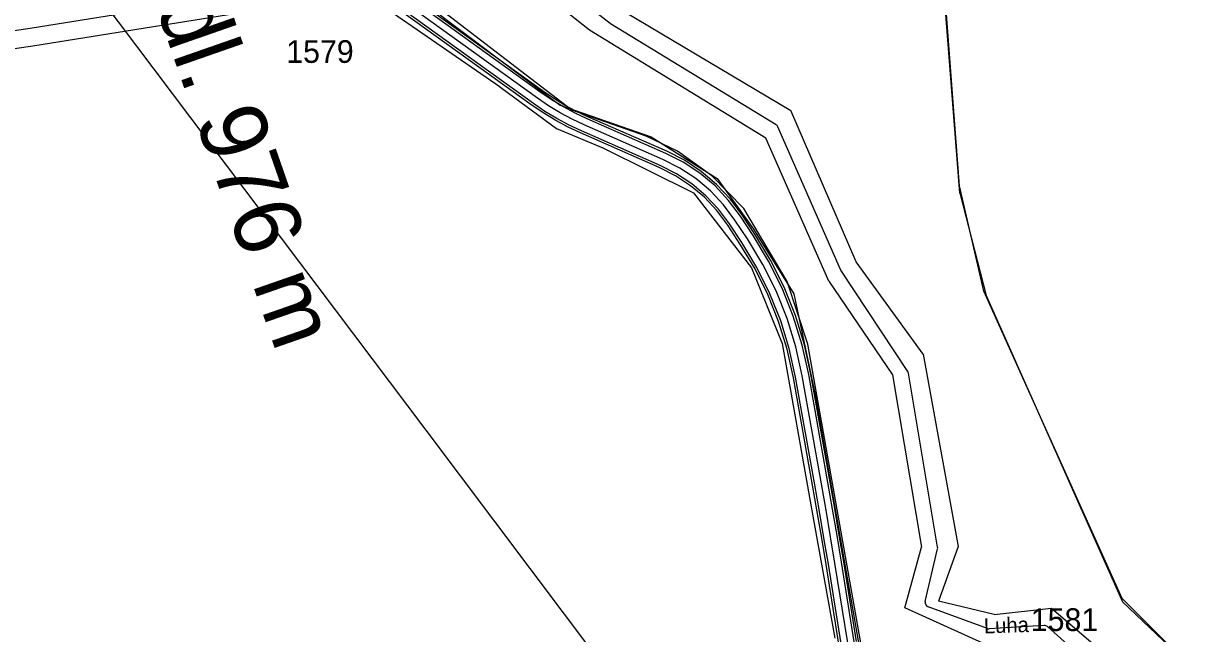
# Model space of a CAD drawing. Extents: x -510185 to -506993, y -1126306 to -1123642.
# Drawn here: x -508784.2 to -508521.1, y -1125749.7 to -1125612.6 of the extents above; entities that cross this region are included whole.
import ezdxf

# ---------------------------------------------------------------- set-up
doc = ezdxf.new("R2010")
doc.units = 0
for name, color, linetype in [('parcelni hranice', 7, 'Continuous'), ('popis cesty', 7, 'Continuous'), ('u_cesta45', 7, 'Continuous'), ('u_osa45', 7, 'Continuous'), ('u_plyn ochranné pásmo', 7, 'Continuous'), ('u_plyn VTL', 7, 'Continuous'), ('u_tok Luha', 7, 'Continuous'), ('u_vysadba_oseti', 7, 'Continuous'), ('ˇ2', 7, 'Continuous'), ('ˇ7', 7, 'Continuous')]:
    doc.layers.add(name, color=color, linetype=linetype)

msp = doc.modelspace()

# ---------------------------------------------------------------- linework, layer by layer
at = {"layer": 'parcelni hranice'}
for p, q in [((-508656.79, -1125614.14), (-508689.34, -1125588.22)), ((-508573.48, -1125650.78), (-508577.96, -1125593.25)), ((-508769.78, -1125602.99), (-508693.62, -1125704.05)), ((-508660.76, -1125632.06), (-508698.05, -1125603.52)), ((-508654, -1125606.86), (-508611.54, -1125632.17)), ((-508704.46, -1125607.9), (-508677.88, -1125626.19)), ((-508617.14, -1125638.37), (-508656.79, -1125614.14)), ((-508677.88, -1125626.19), (-508664.23, -1125636.19)), ((-508644.09, -1125637.9), (-508660.76, -1125632.06)), ((-508596.84, -1125666.2), (-508611.54, -1125632.17)), ((-508664.23, -1125636.19), (-508653.81, -1125640.54)), ((-508637.04, -1125641.34), (-508644.09, -1125637.9)), ((-508602.93, -1125670.51), (-508617.14, -1125638.37)), ((-508653.81, -1125640.54), (-508633.42, -1125650.65)), ((-508629.31, -1125646.84), (-508637.04, -1125641.34)), ((-508622.09, -1125654.23), (-508629.31, -1125646.84)), ((-508633.42, -1125650.65), (-508620.35, -1125667.54)), ((-508573.48, -1125650.78), (-508567.57, -1125673.74)), ((-508612.34, -1125670.63), (-508622.09, -1125654.23)), ((-508620.35, -1125667.54), (-508613.43, -1125684.51)), ((-508581.73, -1125686.94), (-508596.84, -1125666.2)), ((-508607.7, -1125684.72), (-508612.34, -1125670.63)), ((-508602.93, -1125670.51), (-508588.62, -1125691.57)), ((-508567.57, -1125673.74), (-508536.92, -1125742.59)), ((-508613.43, -1125684.51), (-508606.96, -1125721.26)), ((-508594.29, -1125760.02), (-508607.7, -1125684.72)), ((-508581.73, -1125686.94), (-508573.88, -1125730.19)), ((-508588.62, -1125691.57), (-508582.09, -1125730.32)), ((-508693.62, -1125704.05), (-508617.45, -1125805.11)), ((-508606.96, -1125721.26), (-508601.58, -1125750.78)), ((-508585.87, -1125743.98), (-508582.09, -1125730.32)), ((-508573.88, -1125730.19), (-508578.29, -1125742.45)), ((-508567.5, -1125752.28), (-508585.87, -1125743.98)), ((-508565.8, -1125745.45), (-508578.29, -1125742.45)), ((-508565.8, -1125745.45), (-508552.85, -1125744.04)), ((-508552.85, -1125744.04), (-508538.06, -1125756.62)), ((-508522.69, -1125756.07), (-508536.92, -1125742.59))]:
    msp.add_line(p, q, dxfattribs=at)
at = {"layer": 'u_cesta45'}
for points in [[(-508597.23, -1125751.59), (-508600.11, -1125733.68), (-508601.09, -1125727.71), (-508602.1, -1125721.74), (-508603.15, -1125715.79), (-508607.49, -1125691.53), (-508608.95, -1125684.92), (-508610.95, -1125678.43), (-508613.47, -1125672.12), (-508616.5, -1125666.03), (-508620, -1125660.24), (-508622.86, -1125655.92), (-508625.5, -1125652.38), (-508628.56, -1125649.13), (-508631.97, -1125646.26), (-508635.7, -1125643.8), (-508639.63, -1125641.8), (-508657.37, -1125634.03), (-508660.07, -1125632.77), (-508662.68, -1125631.37), (-508665.21, -1125629.83), (-508667.68, -1125628.16), (-508701.21, -1125604.02)], [(-508596.74, -1125751.51), (-508599.62, -1125733.6), (-508600.6, -1125727.63), (-508601.61, -1125721.66), (-508602.66, -1125715.7), (-508607, -1125691.43), (-508608.46, -1125684.8), (-508610.48, -1125678.26), (-508613.02, -1125671.91), (-508616.06, -1125665.79), (-508619.58, -1125659.97), (-508622.45, -1125655.63), (-508625.12, -1125652.06), (-508628.22, -1125648.77), (-508631.67, -1125645.86), (-508635.44, -1125643.36), (-508639.42, -1125641.34), (-508657.16, -1125633.58), (-508659.85, -1125632.32), (-508662.43, -1125630.93), (-508664.94, -1125629.41), (-508667.39, -1125627.75), (-508700.91, -1125603.62)], [(-508600.69, -1125752.11), (-508603.57, -1125734.24), (-508604.54, -1125728.29), (-508605.55, -1125722.34), (-508606.6, -1125716.4), (-508610.92, -1125692.22), (-508612.33, -1125685.82), (-508614.25, -1125679.6), (-508616.67, -1125673.55), (-508619.57, -1125667.72), (-508622.96, -1125662.11), (-508625.72, -1125657.93), (-508628.18, -1125654.63), (-508630.97, -1125651.68), (-508634.07, -1125649.07), (-508637.46, -1125646.83), (-508641.13, -1125644.96), (-508658.82, -1125637.22), (-508661.64, -1125635.89), (-508664.42, -1125634.41), (-508667.11, -1125632.78), (-508669.69, -1125631.02), (-508703.32, -1125606.82)], [(-508600.2, -1125752.04), (-508603.07, -1125734.16), (-508604.05, -1125728.2), (-508605.06, -1125722.26), (-508606.11, -1125716.31), (-508610.43, -1125692.12), (-508611.85, -1125685.69), (-508613.78, -1125679.43), (-508616.21, -1125673.34), (-508619.13, -1125667.48), (-508622.54, -1125661.84), (-508625.31, -1125657.65), (-508627.8, -1125654.31), (-508630.63, -1125651.32), (-508633.77, -1125648.67), (-508637.21, -1125646.39), (-508640.92, -1125644.51), (-508658.61, -1125636.77), (-508661.42, -1125635.45), (-508664.17, -1125633.97), (-508666.84, -1125632.36), (-508669.4, -1125630.61), (-508703.02, -1125606.42)]]:
    msp.add_lwpolyline(points, dxfattribs=at)
at = {"layer": 'u_osa45'}
msp.add_lwpolyline([(-508598.72, -1125751.81), (-508601.59, -1125733.92), (-508602.57, -1125727.96), (-508603.58, -1125722), (-508604.63, -1125716.05), (-508608.96, -1125691.82), (-508610.4, -1125685.31), (-508612.37, -1125678.93), (-508614.84, -1125672.73), (-508617.82, -1125666.76), (-508621.27, -1125661.04), (-508624.08, -1125656.78), (-508626.65, -1125653.35), (-508629.59, -1125650.23), (-508632.87, -1125647.46), (-508636.45, -1125645.1), (-508640.28, -1125643.15), (-508657.99, -1125635.4), (-508660.74, -1125634.11), (-508663.42, -1125632.67), (-508666.03, -1125631.1), (-508668.54, -1125629.38), (-508702.11, -1125605.22)], dxfattribs=at)
at = {"layer": 'u_plyn ochranné pásmo'}
msp.add_lwpolyline([(-508215.72, -1125512.32), (-508356.96, -1125534.53), (-508472.31, -1125551.39), (-508597.98, -1125572.31), (-508671.06, -1125599.9), (-508782.04, -1125617.67), (-508874.62, -1125631.18), (-508973.18, -1125645.99), (-509071.95, -1125660.86), (-509155.57, -1125674.9), (-509219.48, -1125685.66), (-509328.98, -1125704.41)], dxfattribs=at)
at = {"layer": 'u_plyn VTL'}
msp.add_lwpolyline([(-508672.09, -1125596.01), (-508782.65, -1125613.72), (-508875.21, -1125627.22), (-508973.78, -1125642.03), (-509072.58, -1125656.91), (-509156.23, -1125670.95), (-509220.15, -1125681.72)], dxfattribs=at)
at = {"layer": 'u_tok Luha'}
for p, q in [((-508652.19, -1125612.59), (-508703.37, -1125572.82)), ((-508614.84, -1125635.36), (-508652.1, -1125612.66)), ((-508600.36, -1125667.89), (-508614.44, -1125635.81)), ((-508585.18, -1125690.84), (-508600.28, -1125668.04)), ((-508578.49, -1125730.31), (-508585.03, -1125691.23)), ((-508581.26, -1125742.56), (-508578.5, -1125730.7)), ((-508567.28, -1125748.63), (-508580.63, -1125743.73)), ((-508554.5, -1125747.92), (-508566.87, -1125748.69)), ((-508541.92, -1125758.71), (-508553.78, -1125748.18))]:
    msp.add_line(p, q, dxfattribs=at)
for centre, start, end in [((-508651.58, -1125611.8), 232.1477, 238.6429), ((-508615.36, -1125636.22), 23.6973, 58.6429), ((-508599.45, -1125667.49), 203.6973, 213.5213), ((-508586.01, -1125691.39), 9.4969, 33.5213), ((-508579.47, -1125730.47), 346.8866, 9.4969), ((-508580.29, -1125742.79), 166.8866, 249.8293), ((-508566.93, -1125747.7), 249.8293, 273.5562), ((-508554.44, -1125748.92), 48.3665, 93.5562)]:
    msp.add_arc(centre, 1, start, end, dxfattribs=at)
at = {"layer": 'u_vysadba_oseti'}
for points in [[(-508767.46, -1125346.61), (-508757.41, -1125358.61), (-508747.36, -1125374.17), (-508745.73, -1125388.11), (-508747.68, -1125398.16), (-508754.81, -1125406.59), (-508777.51, -1125426.69), (-508778.48, -1125432.2), (-508749.95, -1125485.37), (-508739.57, -1125510.01), (-508727.9, -1125560.91), (-508714.29, -1125586.85), (-508694.83, -1125607.27), (-508663.39, -1125630.94), (-508642.96, -1125638.07), (-508628.05, -1125647.47), (-508619.94, -1125658.82), (-508610.87, -1125673.41), (-508606, -1125696.1), (-508595.3, -1125757.38)], [(-508522.68, -1125756.08), (-508536.95, -1125741.82), (-508568.07, -1125672.76), (-508573.58, -1125649.09), (-508577.8, -1125593.65), (-508573.91, -1125572.26), (-508717.53, -1125450.03), (-508721.74, -1125431.23), (-508715.91, -1125393.62), (-508711.69, -1125378.38), (-508714.93, -1125351.8)]]:
    msp.add_lwpolyline(points, dxfattribs=at)

# ---------------------------------------------------------------- texts
at = {"layer": 'popis cesty'}
msp.add_text('SO27 Polní cesta PC 45b - dl. 976 m', height=15, rotation=289.2124, dxfattribs=at).set_placement((-508835.45, -1125376.2))
at = {"layer": 'ˇ2'}
for s, p in [('1579', (-508725.04, -1125621.46)), ('1581', (-508557.53, -1125749.16))]:
    msp.add_text(s, height=5.1, dxfattribs=at).set_placement(p)
at = {"layer": 'ˇ7'}
msp.add_text('Luha', height=3.4, rotation=1.7762, dxfattribs=at).set_placement((-508568.03, -1125749.71))

doc.saveas('drawing.dxf')
